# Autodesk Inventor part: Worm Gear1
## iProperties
Created: 2011-05
Part Number: Worm Gear1
Material: Steel, Mild
Document SubType Name: Modeling
Designer: 904Chiaki
Categories: <?xml version="1.0" encoding="UTF-16"?> <MemberInstance><Categories><FamilyTemplate><FamilyTemplateParameter ValueType="xs:double" Id="1" ObjectReferenceKey="da
Density: 7.86 g/cm^3
Mass: 36271.6 g
Surface Area: 4778.59 cm^2
Volume: 4614.7 cm^3
CustomPartVersion: 1
Author: 904Chiaki
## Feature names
1. Base Body [Revolution]
2. Base Body2 [Revolution]
3. Extrusion1
4. Mirror1
5. Extrusion2
6. Extrusion3
7. Fillet3
8. Extrusion4
9. Extrusion5
10. Chamfer2
11. Fillet4
